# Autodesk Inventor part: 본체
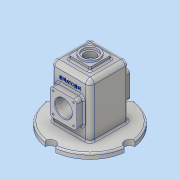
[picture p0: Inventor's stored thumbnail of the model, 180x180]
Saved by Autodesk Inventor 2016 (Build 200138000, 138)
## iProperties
Created: 2018-07
Part Number: 본체
Material: 알루미늄 6061
Document SubType Name: Modeling
Designer: 605-17
Density: 2.7 g/cm^3
Appearance: 알루미늄 - 평지
Mass: 909.367 g
Surface Area: 1016.32 cm^2
Volume: 336.803 cm^3
Author: 605-17
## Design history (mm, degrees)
sketch "스케치1"
  geometry: L1 (-37, 55)-(37, 55); L2 (37, 55)-(37, -55); L3 (37, -55)-(-37, -55); L4 (-37, -55)-(-37, 55); 3 further points
  constraints: 8 end point, 2 midpoint, 2 parallel, 1 horizontal, 1 horizontal alignment, 1 perpendicular, 1 vertical alignment
  dimensions: "d0" = 74 distance of L1.start L1.end; "d1" = 110 distance of L1.end L2.end
extrude "돌출1" new body sketch "스케치1" stored distance "d2" = 74; taper "d3" = 0 deg
fillet "모깎기1" dims "d4" = 8
fillet "모깎기2" dims "d5" = 8
feature "쉘1" dims "d6" = 5
node "작업 평면1"
sketch "스케치2"
  geometry: L1 (-25, 25)-(25, 25); L2 (25, 25)-(25, -25); L3 (25, -25)-(-25, -25); L4 (-25, -25)-(-25, 25); 3 further points
  constraints: 8 end point, 2 midpoint, 2 parallel, 2 perpendicular, 1 horizontal, 1 horizontal alignment, 1 vertical alignment
  dimensions: "d8" = 50 distance of L1.start L1.end
extrude "돌출2" join sketch "스케치2" stored distance "d9" = 74; taper "d10" = 0 deg
sketch "스케치3"
  geometry: L1 (0, 50)-(0, -50); L2 (25, 32)-(22.452, 25); L3 (22.452, 25)-(16, 25); L4 (25, 32)-(16, 32); L5 (0, 50)-(16, 50); L6 (16, 50)-(16, 32); L7 (-55, 32)-(47, 32) reference; L8 (0, 0)-(16, 0); L9 (16, 0)-(16, 25); 1 further point
  constraints: 16 end point, 2 horizontal, 2 perpendicular, 1 coincident, 1 horizontal alignment, 1 midpoint, 1 vertical, 1 vertical alignment
  dimensions: "d11" = 100 distance of L1.start L1.end; "d14" = 110 deg angle of L2 L3; "d15" = 50 diameter of L2.start L1; "d18" = 9 distance of L2.start L4.end; "d19" = 32 diameter of L9 L1; "d20" = 6.45221 distance of L2.end L3.end; "d21" = 16 distance of L1.start L5.end
revolve "회전1" sketch "스케치3" stored, may be unused: angle "d22" = 90 deg
sketch "스케치4"
  geometry: C1 r 16 at (0, 0); 1 further point
  constraints: 1 centre point, 1 coincident
  dimensions: "d23" = 32 diameter of C1
extrude "돌출3" cut sketch "스케치4" distance "d24" = 100; taper "d25" = 0 deg
node "작업 평면2"
sketch "스케치5"
  geometry: L1 (29, 32)-(-29, 32) reference; L2 (-32, 29)-(-32, -29) reference; L3 (-29, -32)-(29, -32) reference; L4 (32, -29)-(32, 29) reference; L5 (-29, -37)-(29, -37) reference; L6 (-37, 29)-(-37, -29) reference; L7 (29, 37)-(-29, 37) reference; L8 (37, 29)-(37, -29) reference; A1 r 10 centre (0, -75) between (9.978, -74.333) and (-9.978, -74.333); A2 r 10 centre (-75, 0) between (-74.333, -9.978) and (-74.333, 9.978); A3 r 10 centre (0, 75) between (-9.978, 74.333) and (9.978, 74.333); A4 r 10 centre (75, 0) between (74.333, 9.978) and (74.333, -9.978); A5 r 75 centre (0, 0) between (74.333, 9.978) and (9.978, 74.333); A6 r 75 centre (0, 0) between (-9.978, 74.333) and (-74.333, 9.978); A7 r 75 centre (0, 0) between (-74.333, -9.978) and (-9.978, -74.333); A8 r 75 centre (0, 0) between (9.978, -74.333) and (74.333, -9.978); A9 r 3 centre (29, 29) between (32, 29) and (29, 32) reference; A10 r 3 centre (-29, 29) between (-29, 32) and (-32, 29) reference; A11 r 3 centre (-29, -29) between (-32, -29) and (-29, -32) reference; A12 r 3 centre (29, -29) between (29, -32) and (32, -29) reference; A13 r 8 centre (29, -29) between (29, -37) and (37, -29) reference; A14 r 8 centre (-29, -29) between (-37, -29) and (-29, -37) reference; A15 r 8 centre (-29, 29) between (-29, 37) and (-37, 29) reference; A16 r 8 centre (29, 29) between (37, 29) and (29, 37) reference; 1 further point
  constraints: 16 point on circle, 8 centre point, 3 concentric, 3 vertical alignment, 2 horizontal alignment, 1 coincident
  dimensions: "d28" = 20 diameter of A1; "d29" = 20 diameter of A2; "d30" = 20 diameter of A3; "d31" = 20 diameter of A4; "d32" = 75 radius of A5; "d33" = 75 distance of point (0, 0) A1.centre; "d34" = 75 distance of point (0, 0) A3.centre; "d35" = 75 distance of point (0, 0) A4.centre; "d36" = 75 distance of point (0, 0) A2.centre
extrude "돌출4" join sketch "스케치5" distance "d37" = 10; taper "d38" = 0 deg
node "작업 평면3"
sketch "스케치6"
  geometry: L1 (20, -20)-(-20, -20); L2 (-20, -20)-(-20, 20); L3 (-20, 20)-(20, 20); L4 (20, 20)-(20, -20); 3 further points
  constraints: 8 end point, 2 midpoint, 2 parallel, 2 perpendicular, 1 horizontal, 1 horizontal alignment, 1 vertical alignment
  dimensions: "d40" = 40 distance of L1.end L2.end
extrude "돌출5" join sketch "스케치6" stored distance "d41" = 10; taper "d42" = 0 deg
sketch "스케치7"
  geometry: C1 r 17.5 at (0, 0); 1 further point
  constraints: 1 centre point, 1 coincident
  dimensions: "d43" = 35 diameter of C1
extrude "돌출6" join sketch "스케치7" distance "d44" = 3; taper "d45" = 0 deg
hole "구멍1" diameter "d48" = 21; stored, may be unused: countersink angle "d52" = 90 deg, drill point angle "d54" = 118 deg; dims "d46" = 10, "d47" = 10, "d49" = 6, "d50" = 28, "d51" = 4, "d53" = 50
fillet "모깎기3" dims "d55" = 6
sketch "스케치8"
  geometry: A1 r 6 centre (-19, 19) between (-19, 25) and (-25, 19) reference; A2 r 6 centre (19, 19) between (25, 19) and (19, 25) reference; A3 r 6 centre (19, -19) between (19, -25) and (25, -19) reference; A4 r 6 centre (-19, -19) between (-25, -19) and (-19, -25) reference; 1 further point
hole "구멍2" sketch "스케치8" at (-19, 19), (19, 19), (19, -19), (-19, -19) diameter "d56" = 3.242; stored, may be unused: countersink angle "d60" = 90 deg, drill point angle "d62" = 118 deg; dims "d57" = 8, "d58" = 28, "d59" = 4, "d61" = 10
fillet "모깎기4" dims "d63" = 3
fillet "모깎기5" dims "d64" = 3
fillet "모깎기6" dims "d65" = 3
fillet "모깎기7" dims "d66" = 3
chamfer "모따기1" distance "d67" = 1; stored, may be unused: second distance "d68" = 2, angle "d69" = 45 deg
sketch "스케치9"
  geometry: L1 (-23.66, 39.42)-(23.66, 39.42); L2 (23.66, 39.42)-(23.66, 30.58); L3 (23.66, 30.58)-(-23.66, 30.58); L4 (-23.66, 30.58)-(-23.66, 39.42); L5 (17.5, 65)-(-17.5, 65) reference; L6 (37, -42)-(37, 47) reference; 4 further points
  constraints: 2 midpoint, 1 horizontal alignment, 1 vertical, 1 vertical alignment, 2 other
  dimensions: "d70" = 47.32037 distance of L1.start L1.end; "d71" = 8.84007 distance of L1.end L2.end; "d72" = 30 distance from line of L5 point (0, 35); "d73" = 37 distance from line of L6 point (0, 35)
feature "엠보싱1" sketch "스케치9" dims "d0" = 74, "d1" = 110, "d74" = 0.5, "d75" = 0
node "솔리드1"
mirror "대칭1"
mirror "대칭2"
mirror "대칭3"
node "투영된 루프1"
other parameters: "d16" = 32, "d26" = -55, "d39" = 62
